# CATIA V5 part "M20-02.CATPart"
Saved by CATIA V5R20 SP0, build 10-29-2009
Part number: M20-02
Revision: ANY
Definition: UNKNOWN
Nomenclature: M20-02
Source: Unknown
Bounding box of the stored display mesh (mm): x -12.5 to 12.5, y -12.31 to 12.31, z 0 to 170
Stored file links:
  C:\Users\Utente\Desktop\IO LAVORO\3D X SITO CF\X 3D SITO CF 27-09-2020\740T\740T-20\M20-02.CATPart
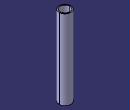
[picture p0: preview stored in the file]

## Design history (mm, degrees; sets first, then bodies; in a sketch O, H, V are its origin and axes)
Body1 "NONE" (main body)
  Solid1: solid without history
